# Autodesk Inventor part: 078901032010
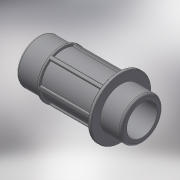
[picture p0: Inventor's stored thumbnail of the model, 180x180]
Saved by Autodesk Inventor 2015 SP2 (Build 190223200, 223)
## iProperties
Created: 2018-02
Part Number: 078901032010
Material: Generic
Description: PLASSON THREADED MALE ADAPTOR 32-1"
Document SubType Name: Modeling
Designer: KIM
Density: 1 g/cm^3
Appearance: Default
Author: KIM
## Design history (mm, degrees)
derived "078901.ipt"
feature "Solid1::078901.ipt"
tag "TaggingFeature1"
body "Solid1"
other parameters: "d4" = 1.66245, "d14" = 2.65992, "d15" = 1.32996, "d17" = 0, "d20" = 360 deg, "d41" = 33.249, "d45" = 36.5739, "d46" = 23.2743, "d47" = 2, "d77" = 87, "d78" = 32, "d85" = 0.33249, "d91" = 17.4, "d103" = 20.01, "d104" = 46, "d105" = 0.33249, "R_" = 33.249, "E_" = 46, "l_" = 87, "d_" = 32
